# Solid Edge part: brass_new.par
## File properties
Author: CADSoft
Template: Sync Iso Part.par
Last saved by: Sarvanan
Revision: 7
Application: Solid Edge
Accuracy: 0.990
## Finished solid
Body 1: solid body, 16 faces, 18 edges, 0 vertices.
  Faces by surface: cylinder 9, plane 7
  Edges by curve: circle 14, intersection 4
Bounding box of the edges (mm): 64.000 x 64.000 x 64.000, from (-32, -32, -32) to (32, 32, 32).
Cylindrical faces by radius (mm): R3 x2, R4 x1, R16 x1, R22 x1, R24 x2, R32 x2
Planar faces by outward normal: +x 3, +z 1, -x 3
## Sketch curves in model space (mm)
line (-32, 0, 0) -> (32, 0, 0)
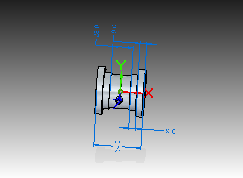
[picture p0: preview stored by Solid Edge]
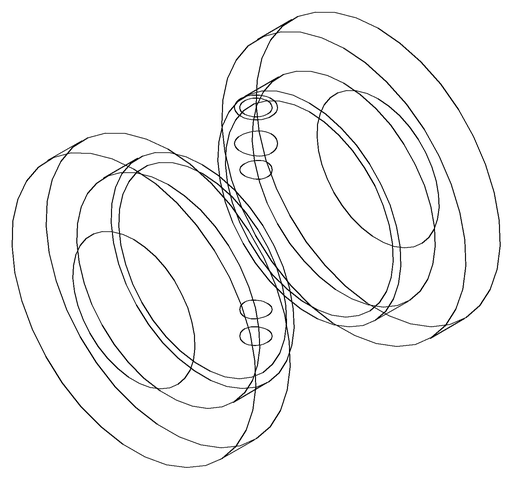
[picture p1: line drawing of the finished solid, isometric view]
